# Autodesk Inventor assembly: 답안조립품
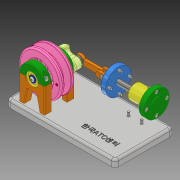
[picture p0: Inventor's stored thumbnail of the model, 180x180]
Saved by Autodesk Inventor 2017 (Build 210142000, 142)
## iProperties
Part Number: 답안조립품
Material: 일반
Document SubType Name: Assembly
Designer: MRC
Mass: 875.591 g
Surface Area: 889.135 cm^2
Volume: 230.182 cm^3
Density: 3.80391 g/cm^3
Author: MRC
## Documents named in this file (19)
- C:\Users\MRC\Desktop\630206V1007\답안조립품.iam
- C:\Users\MRC\Desktop\630206V1007\플레이트.ipt
- C:\Users\MRC\Desktop\630206V1007\V-벨트풀리.ipt
- C:\Users\MRC\Desktop\630206V1007\둥근머리볼트 M3x12.ipt
- C:\Users\MRC\Desktop\630206V1007\베어링 608.ipt
- C:\Users\MRC\Desktop\630206V1007\베어링커버-A.ipt
- C:\Users\MRC\Desktop\630206V1007\볼트 M3x8.ipt
- C:\Users\MRC\Desktop\630206V1007\볼트 M3x12.ipt
- C:\Users\MRC\Desktop\630206V1007\스페이서.ipt
- C:\Users\MRC\Desktop\630206V1007\와셔.ipt
- C:\Users\MRC\Desktop\630206V1007\지지대-A.ipt
- C:\Users\MRC\Desktop\630206V1007\커넥팅로드-A.ipt
- C:\Users\MRC\Desktop\630206V1007\커넥팅로드-B.ipt
- C:\Users\MRC\Desktop\630206V1007\크랭크축.ipt
- C:\Users\MRC\Desktop\630206V1007\플랜지.ipt
- C:\Users\MRC\Desktop\630206V1007\피스톤.ipt
- C:\Users\MRC\Desktop\630206V1007\하우징.ipt
- C:\Users\MRC\Desktop\630206V1007\하우징커버-A.ipt
- C:\Users\MRC\Desktop\630206V1007\하우징커버-B.ipt
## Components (7 placed, 7 different names)
1. 플레이트:1 — 구동
2. V-벨트풀리:1
3. 플랜지:1
4. 피스톤:1
5. 하우징:1
6. 하우징커버-A:1
7. 하우징커버-B:1
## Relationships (1: Angle 1)
- 구동 [Angle]: 플레이트:1
